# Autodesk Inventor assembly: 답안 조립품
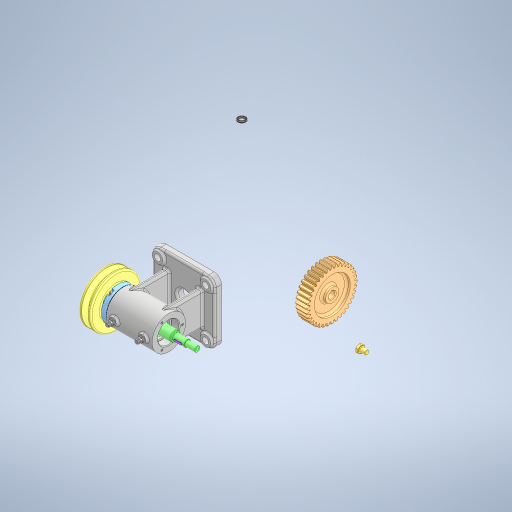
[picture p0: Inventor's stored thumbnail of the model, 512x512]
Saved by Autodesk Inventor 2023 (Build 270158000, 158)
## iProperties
Created: 2025-10
Part Number: 답안 조립품
Document SubType Name: Assembly
Designer: home
Author: home
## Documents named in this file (17)
- C:\Users\home\Desktop\751003V1010\답안 조립품.iam
- C:\Users\home\Desktop\751003V1010\본체.ipt
- C:\Users\home\Desktop\751003V1010\6각 구멍붙이 볼트 M4x10.ipt
- C:\Users\home\Desktop\751003V1010\6각 너트 M8x1.ipt
- C:\Users\home\Desktop\751003V1010\6각 머리 볼트 M6x0.75x8.ipt
- C:\Users\home\Desktop\751003V1010\V 벨트 풀리.ipt
- C:\Users\home\Desktop\751003V1010\가스켓.ipt
- C:\Users\home\Desktop\751003V1010\그리스 니플 M6x0.75.ipt
- C:\Users\home\Desktop\751003V1010\깊은 홈 볼 베어링 6002.ipt
- C:\Users\home\Desktop\751003V1010\스퍼 기어.ipt
- C:\Users\home\Desktop\751003V1010\스프링 와셔 M8.ipt
- C:\Users\home\Desktop\751003V1010\실링.ipt
- C:\Users\home\Desktop\751003V1010\오일 실 15 25 4.ipt
- C:\Users\home\Desktop\751003V1010\축.ipt
- C:\Users\home\Desktop\751003V1010\커버.ipt
- C:\Users\home\Desktop\751003V1010\평 와셔 M8.ipt
- C:\Users\home\Desktop\751003V1010\평행 키 3x3x12.ipt
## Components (9 placed, 6 different names)
1. 6각 구멍붙이 볼트 M4x10:1
2. 6각 너트 M8x1:1
3. 6각 머리 볼트 M6x0.75x8:1
4. V 벨트 풀리:1 — 각도:2
5. 가스켓:1
6. 그리스 니플 M6x0.75:1
7. 그리스 니플 M6x0.75:2
8. 6각 구멍붙이 볼트 M4x10:2
9. 6각 구멍붙이 볼트 M4x10:3
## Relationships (1: Angle 1)
- 각도:2 [Angle]: V 벨트 풀리:1
